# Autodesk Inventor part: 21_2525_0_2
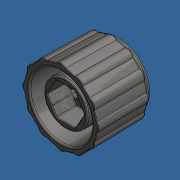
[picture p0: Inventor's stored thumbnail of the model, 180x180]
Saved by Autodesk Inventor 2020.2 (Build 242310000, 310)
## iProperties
Part Number: 21_2525_0_2
Material: ABS Plastic
Document SubType Name: Modeling
Designer: amoles
Appearance: Light Gray
Mass: 26.0572 g
Surface Area: 148.587 cm^2
Volume: 24.5822 cm^3
Density: 1.06 g/cm^3
Author: amoles
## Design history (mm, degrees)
feature "Base1"
body "Solid1"
